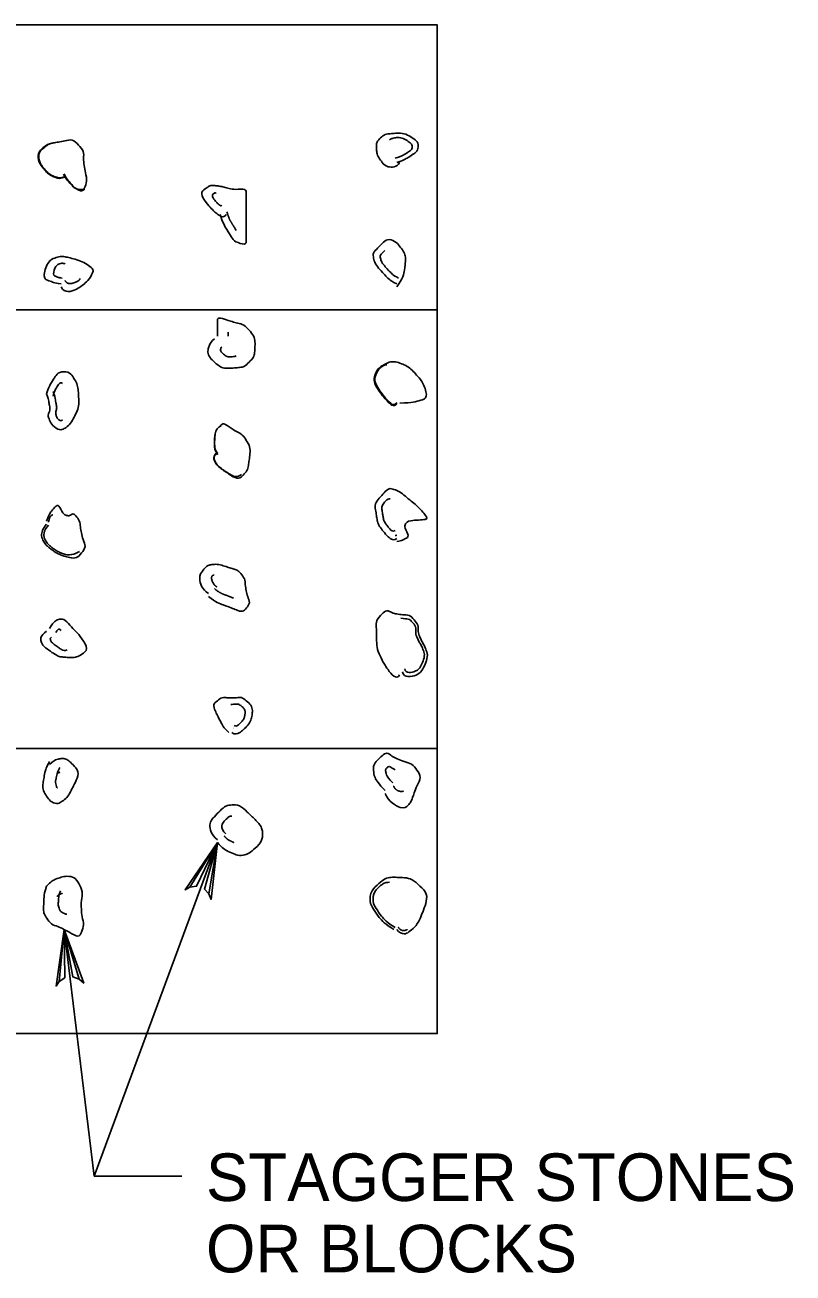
# Model space of a CAD drawing. Extents: x 636183 to 639890, y 299162 to 300538.
# Drawn here: x 638413.2 to 638461.6, y 300152.3 to 300230.9 of the extents above; entities that cross this region are included whole.
import ezdxf

# ---------------------------------------------------------------- set-up
doc = ezdxf.new("R2010")
doc.units = 0
doc.layers.add('Default', color=7, linetype='Continuous')

msp = doc.modelspace()

# ---------------------------------------------------------------- linework, layer by layer
at = {"layer": 'Default'}
for points in [[(638276.121, 300230.921), (638276.121, 300212.959), (638439.159, 300212.959), (638439.159, 300230.921), (638276.121, 300230.921)], [(638276.121, 300212.959), (638276.121, 300185.325), (638439.159, 300185.325), (638439.159, 300212.959), (638276.121, 300212.959)], [(638276.121, 300167.363), (638276.121, 300185.325), (638439.159, 300185.325), (638439.159, 300167.363), (638276.121, 300167.363)], [(638425.297, 300179.395), (638417.541, 300158.382)], [(638423.567, 300176.592), (638423.264, 300176.418), (638425.297, 300179.395), (638423.567, 300176.592), (638423.985, 300176.645), (638425.297, 300179.395), (638424.478, 300176.467), (638424.766, 300176.165), (638425.297, 300179.395), (638424.904, 300175.811), (638424.766, 300176.165)], [(638415.324, 300170.642), (638415.129, 300170.351), (638415.629, 300173.922), (638415.324, 300170.642), (638415.675, 300170.875), (638415.629, 300173.922), (638416.195, 300170.934), (638416.587, 300170.791), (638415.629, 300173.922), (638416.869, 300170.536), (638416.587, 300170.791)], [(638423.067, 300158.382), (638417.541, 300158.382), (638415.629, 300173.922)]]:
    msp.add_lwpolyline(points, dxfattribs=at)
for points, degree in [([(638415.639, 300221.323), (638415.466, 300221.243), (638415.253, 300221.255), (638415.072, 300221.323), (638414.773, 300221.434), (638414.529, 300221.635), (638414.324, 300221.882), (638414.035, 300222.23), (638413.949, 300222.886), (638414.324, 300223.195), (638414.567, 300223.395), (638414.84, 300223.459), (638415.114, 300223.51)], 3), ([(638415.629, 300221.35), (638415.462, 300221.272), (638415.257, 300221.284), (638415.081, 300221.35), (638414.789, 300221.46), (638414.551, 300221.656), (638414.351, 300221.898), (638414.072, 300222.237), (638413.985, 300222.865), (638414.351, 300223.174), (638414.634, 300223.412), (638414.948, 300223.491), (638415.263, 300223.54), (638415.678, 300223.604), (638416.172, 300223.745), (638416.541, 300223.356), (638416.921, 300222.956), (638416.835, 300222.512), (638416.905, 300222.08), (638416.982, 300221.605), (638417.106, 300221.068), (638416.905, 300220.62), (638416.802, 300220.389), (638416.342, 300220.614), (638416.175, 300220.802), (638415.973, 300221.03), (638415.761, 300221.254), (638415.629, 300221.532)], 3), ([(638436.79, 300222.262), (638436.619, 300221.936), (638435.949, 300221.93), (638435.694, 300222.262), (638435.465, 300222.56), (638435.338, 300222.866), (638435.33, 300223.174), (638435.325, 300223.355), (638435.338, 300223.543), (638435.512, 300223.722), (638435.807, 300224.027), (638436.116, 300224.058), (638436.424, 300224.086), (638436.841, 300224.124), (638437.291, 300224.017), (638437.702, 300223.722), (638437.984, 300223.52), (638437.954, 300222.983), (638437.702, 300222.81), (638437.363, 300222.578), (638437.001, 300222.373), (638436.606, 300222.262)], 3), ([(638436.152, 300223.685), (638436.247, 300223.747), (638436.342, 300223.78), (638436.438, 300223.798), (638436.759, 300223.857), (638437.109, 300223.745), (638437.428, 300223.517), (638437.595, 300223.398), (638437.577, 300223.08), (638437.428, 300222.978), (638437.145, 300222.784), (638436.842, 300222.613), (638436.511, 300222.52)], 3), ([(638416.933, 300220.583), (638416.763, 300220.518), (638416.335, 300220.577), (638416.159, 300220.777), (638415.955, 300221.008), (638415.738, 300221.236), (638415.604, 300221.518)], 3), ([(638425.845, 300218.978), (638425.7, 300218.696), (638425.166, 300219.093), (638424.93, 300219.344), (638424.613, 300219.684), (638424.172, 300220.348), (638424.567, 300220.62), (638424.738, 300220.739), (638424.926, 300220.824), (638425.115, 300220.802), (638425.418, 300220.766), (638425.723, 300220.697), (638426.027, 300220.62), (638426.403, 300220.525), (638427.12, 300220.641), (638427.12, 300220.256), (638427.12, 300219.891), (638427.12, 300219.526), (638427.12, 300219.16), (638427.12, 300218.552), (638427.12, 300217.944), (638427.12, 300217.336), (638427.12, 300217.026), (638426.375, 300217.256), (638426.209, 300217.521), (638425.917, 300217.985), (638425.631, 300218.454), (638425.479, 300218.978)], 3), ([(638425.582, 300219.57), (638425.538, 300219.484), (638425.375, 300219.605), (638425.303, 300219.681), (638425.142, 300219.852), (638424.914, 300220.198), (638425.119, 300220.33), (638425.127, 300220.335), (638425.134, 300220.338), (638425.142, 300220.337), (638425.171, 300220.333), (638425.199, 300220.327), (638425.228, 300220.321)], 3), ([(638426.487, 300217.97), (638426.257, 300218.349), (638426.026, 300218.719), (638425.902, 300219.14)], 2), ([(638436.606, 300214.601), (638436.329, 300214.733), (638436.107, 300214.898), (638435.876, 300215.149), (638435.542, 300215.509), (638435.231, 300215.876), (638435.148, 300216.243), (638435.081, 300216.539), (638435.406, 300216.862), (638435.694, 300217.154), (638435.995, 300217.46), (638436.518, 300217.311), (638436.79, 300216.973), (638437.031, 300216.673), (638437.167, 300216.369), (638437.154, 300216.061), (638437.13, 300215.516), (638436.992, 300214.949), (638436.606, 300214.419)], 3), ([(638415.445, 300214.601), (638415.196, 300214.633), (638414.95, 300214.702), (638414.715, 300214.783), (638414.246, 300214.945), (638414.603, 300216.072), (638415.081, 300216.243), (638415.371, 300216.346), (638415.699, 300216.319), (638415.993, 300216.243), (638416.442, 300216.126), (638416.905, 300215.96), (638417.269, 300215.695), (638417.571, 300215.474), (638417.197, 300214.857), (638416.905, 300214.601), (638416.533, 300214.274), (638415.651, 300213.975), (638415.445, 300214.419)], 3), ([(638436.728, 300214.967), (638436.507, 300215.071), (638436.33, 300215.203), (638436.145, 300215.402), (638435.886, 300215.682), (638435.644, 300215.967), (638435.579, 300216.252), (638435.544, 300216.402), (638435.709, 300216.564), (638435.855, 300216.712)], 3), ([(638415.512, 300214.965), (638415.393, 300214.98), (638415.274, 300215.013), (638415.162, 300215.052), (638414.898, 300215.144), (638415.096, 300215.789), (638415.369, 300215.874), (638415.478, 300215.908), (638415.597, 300215.897), (638415.708, 300215.874)], 3), ([(638416.629, 300214.937), (638416.629, 300214.777), (638415.811, 300214.54), (638415.692, 300214.822)], 2), ([(638425.297, 300211.317), (638425.297, 300211.621), (638425.297, 300211.925), (638425.297, 300212.229), (638425.297, 300212.533), (638425.925, 300212.319), (638426.209, 300212.229), (638426.589, 300212.108), (638426.969, 300212.061), (638427.302, 300211.683), (638427.618, 300211.326), (638427.682, 300210.949), (638427.668, 300210.587), (638427.657, 300210.279), (638427.598, 300209.973), (638427.302, 300209.675), (638427.007, 300209.377), (638426.7, 300209.335), (638426.39, 300209.311), (638425.973, 300209.278), (638425.531, 300209.302), (638425.115, 300209.675), (638424.806, 300209.951), (638424.672, 300210.304), (638424.749, 300210.587), (638424.8, 300210.777), (638424.93, 300210.977), (638425.115, 300211.135)], 3), ([(638425.974, 300211.317), (638425.974, 300211.395), (638425.974, 300211.473), (638425.974, 300211.552)], 2), ([(638426.483, 300210.078), (638426.44, 300210.047), (638426.397, 300210.032), (638426.354, 300210.025), (638426.115, 300209.989), (638425.858, 300210.019), (638425.619, 300210.235), (638425.527, 300210.318), (638425.488, 300210.423), (638425.511, 300210.509), (638425.522, 300210.55), (638425.549, 300210.594), (638425.589, 300210.628)], 3), ([(638436.626, 300207.057), (638436.44, 300206.768), (638435.91, 300207.302), (638435.657, 300207.639), (638435.349, 300208.048), (638435.106, 300208.564), (638435.279, 300208.959), (638435.382, 300209.194), (638435.599, 300209.4), (638435.857, 300209.537), (638436.214, 300209.726), (638436.637, 300209.692), (638436.988, 300209.537), (638437.361, 300209.372), (638437.656, 300209.099), (638437.925, 300208.786), (638438.269, 300208.388), (638438.615, 300207.409), (638438.116, 300207.266), (638437.681, 300207.142), (638437.238, 300207.11), (638436.794, 300207.077)], 3), ([(638436.606, 300207.121), (638436.43, 300206.85), (638435.932, 300207.352), (638435.694, 300207.669), (638435.397, 300208.065), (638435.163, 300208.563), (638435.33, 300208.945), (638435.427, 300209.168), (638435.623, 300209.386), (638435.876, 300209.493), (638435.911, 300209.508), (638435.948, 300209.5), (638435.984, 300209.493)], 3), ([(638414.533, 300207.669), (638414.644, 300208.064), (638414.847, 300208.426), (638415.081, 300208.763), (638415.291, 300209.065), (638415.946, 300209.093), (638416.175, 300208.763), (638416.417, 300208.415), (638416.523, 300208.047), (638416.541, 300207.669), (638416.562, 300207.246), (638416.556, 300206.814), (638416.357, 300206.391), (638416.178, 300206.009), (638415.905, 300205.632), (638415.629, 300205.479), (638415.378, 300205.34), (638414.87, 300205.676), (638414.715, 300206.027), (638414.583, 300206.328), (638414.775, 300206.643), (638414.715, 300206.939), (638414.666, 300207.184), (638414.624, 300207.43), (638414.533, 300207.669)], 3), ([(638414.939, 300207.52), (638415.021, 300207.814), (638415.151, 300208.087), (638415.346, 300208.335), (638415.387, 300208.386), (638415.482, 300208.374), (638415.535, 300208.335)], 3), ([(638415.528, 300206.041), (638415.444, 300205.905), (638415.187, 300206.124), (638415.146, 300206.271), (638415.08, 300206.509), (638415.193, 300206.758), (638415.146, 300206.992), (638415.09, 300207.269), (638415.042, 300207.548), (638414.939, 300207.819)], 3), ([(638425.297, 300203.837), (638425.136, 300204.129), (638425.102, 300204.448), (638425.115, 300204.749), (638425.128, 300205.068), (638425.21, 300205.403), (638425.479, 300205.661), (638425.684, 300205.859), (638425.988, 300205.613), (638426.209, 300205.479), (638426.551, 300205.271), (638426.884, 300205.115), (638427.12, 300204.749), (638427.381, 300204.346), (638427.354, 300203.892), (638427.302, 300203.474), (638427.263, 300203.155), (638427.19, 300202.829), (638426.938, 300202.562), (638426.654, 300202.259), (638426.17, 300202.519), (638425.845, 300202.744), (638425.541, 300202.953), (638425.239, 300203.184), (638425.115, 300203.474), (638425.045, 300203.635), (638425.14, 300203.883), (638425.297, 300204.022)], 3), ([(638425.313, 300203.847), (638425.154, 300204.135), (638425.118, 300204.451), (638425.131, 300204.749), (638425.144, 300205.062), (638425.207, 300205.42), (638425.49, 300205.643), (638425.505, 300205.654), (638425.523, 300205.636), (638425.538, 300205.629)], 3), ([(638426.812, 300202.601), (638426.543, 300202.373), (638426.141, 300202.563), (638425.852, 300202.76), (638425.549, 300202.964), (638425.255, 300203.193), (638425.133, 300203.478), (638425.066, 300203.635), (638425.159, 300203.876), (638425.31, 300204.01)], 3), ([(638436.606, 300198.548), (638436.361, 300198.379), (638435.943, 300198.773), (638435.694, 300199.096), (638435.463, 300199.394), (638435.379, 300199.695), (638435.33, 300200.008), (638435.274, 300200.361), (638435.207, 300200.746), (638435.512, 300201.102), (638435.805, 300201.443), (638436.127, 300201.754), (638436.424, 300201.65), (638436.79, 300201.521), (638437.154, 300201.215), (638437.518, 300200.92), (638437.874, 300200.631), (638438.209, 300200.285), (638438.429, 300200.008), (638438.667, 300199.71), (638437.31, 300199.73), (638437.154, 300199.46), (638437.051, 300199.282), (638437.431, 300198.685), (638437.154, 300198.548), (638436.978, 300198.461), (638436.795, 300198.4), (638436.606, 300198.366)], 3), ([(638414.533, 300199.642), (638414.642, 300199.986), (638414.84, 300200.334), (638415.081, 300200.556), (638415.288, 300200.746), (638415.55, 300200.08), (638415.811, 300200.008), (638415.968, 300199.965), (638416.223, 300200.167), (638416.357, 300200.008), (638416.64, 300199.672), (638416.651, 300199.289), (638416.723, 300198.914), (638416.803, 300198.498), (638417.049, 300198.034), (638416.723, 300197.636), (638416.44, 300197.29), (638415.966, 300197.343), (638415.629, 300197.454), (638415.382, 300197.536), (638415.138, 300197.648), (638414.899, 300197.818), (638414.673, 300197.979), (638414.483, 300198.154), (638414.351, 300198.366), (638414.163, 300198.669), (638414.263, 300199.183), (638414.533, 300199.46)], 3), ([(638436.509, 300199.057), (638436.374, 300198.963), (638436.143, 300199.182), (638436.005, 300199.361), (638435.83, 300199.587), (638435.766, 300199.815), (638435.728, 300200.052), (638435.687, 300200.313), (638435.649, 300200.6), (638435.864, 300200.862), (638435.967, 300200.988), (638436.083, 300201.068), (638436.203, 300201.065)], 3), ([(638414.648, 300199.596), (638414.699, 300199.768), (638414.753, 300199.97), (638414.922, 300200.054)], 2), ([(638416.601, 300197.74), (638416.319, 300197.585), (638415.94, 300197.484), (638415.648, 300197.581), (638415.419, 300197.656), (638415.192, 300197.761), (638414.971, 300197.919), (638414.769, 300198.063), (638414.6, 300198.219), (638414.483, 300198.407), (638414.313, 300198.68), (638414.402, 300199.144), (638414.646, 300199.393)], 3), ([(638436.601, 300198.771), (638436.573, 300198.757), (638436.544, 300198.747), (638436.514, 300198.741)], 2), ([(638424.749, 300195.082), (638424.312, 300195.356), (638424.07, 300196.143), (638424.385, 300196.542), (638424.522, 300196.716), (638424.717, 300196.878), (638424.93, 300196.906), (638425.291, 300196.953), (638425.668, 300196.846), (638426.027, 300196.724), (638426.29, 300196.634), (638426.549, 300196.597), (638426.757, 300196.36), (638427.051, 300196.024), (638427.044, 300195.636), (638427.12, 300195.264), (638427.193, 300194.912), (638427.394, 300194.498), (638427.12, 300194.17), (638426.893, 300193.897), (638426.485, 300194.062), (638426.209, 300194.17), (638425.713, 300194.363), (638425.188, 300194.542), (638424.749, 300194.9)], 3), ([(638425.274, 300195.504), (638425.047, 300195.632), (638424.865, 300196.2), (638425.082, 300196.261)], 2), ([(638426.314, 300194.799), (638425.906, 300194.969), (638425.473, 300195.11), (638425.11, 300195.402)], 2), ([(638414.715, 300192.892), (638414.856, 300193.132), (638415.068, 300193.374), (638415.263, 300193.44), (638415.594, 300193.553), (638416.016, 300193.066), (638416.357, 300192.71), (638416.747, 300192.303), (638417.205, 300191.548), (638416.723, 300191.25), (638416.426, 300191.066), (638416.113, 300191.044), (638415.811, 300191.068), (638415.568, 300191.088), (638415.324, 300191.099), (638415.081, 300191.25), (638414.665, 300191.511), (638414.245, 300191.832), (638414.169, 300192.164), (638414.131, 300192.333), (638414.336, 300192.568), (638414.533, 300192.71)], 3), ([(638436.79, 300189.974), (638436.594, 300189.596), (638435.935, 300190.424), (638435.694, 300190.886), (638435.409, 300191.432), (638435.332, 300191.983), (638435.33, 300192.528), (638435.328, 300192.959), (638435.281, 300193.399), (638435.694, 300193.806), (638435.977, 300194.086), (638436.31, 300193.864), (638436.606, 300193.806), (638436.98, 300193.733), (638437.405, 300193.77), (638437.702, 300193.44), (638437.997, 300193.111), (638437.918, 300192.693), (638438.066, 300192.346), (638438.17, 300192.101), (638438.329, 300191.861), (638438.429, 300191.616), (638438.588, 300191.229), (638438.458, 300190.736), (638438.248, 300190.338), (638438.037, 300189.941), (638437.046, 300189.734), (638436.972, 300190.156)], 3), ([(638436.859, 300193.544), (638437.101, 300193.486), (638437.374, 300193.513), (638437.568, 300193.307), (638437.849, 300193.009), (638437.771, 300192.606), (638437.909, 300192.282), (638438.008, 300192.049), (638438.161, 300191.821), (638438.257, 300191.589), (638438.393, 300191.255), (638438.282, 300190.83), (638438.1, 300190.488), (638437.937, 300190.181), (638437.17, 300190.02), (638437.112, 300190.348)], 3), ([(638415.114, 300192.639), (638415.168, 300192.73), (638415.247, 300192.832), (638415.323, 300192.846), (638415.36, 300192.853), (638415.403, 300192.803), (638415.441, 300192.768)], 3), ([(638415.823, 300191.54), (638415.684, 300191.472), (638415.467, 300191.551), (638415.316, 300191.667), (638415.09, 300191.841), (638414.807, 300192.02), (638414.761, 300192.222), (638414.753, 300192.259), (638414.798, 300192.311), (638414.842, 300192.342)], 3), ([(638426.027, 300186.327), (638425.691, 300186.636), (638425.491, 300187.04), (638425.297, 300187.421), (638425.162, 300187.685), (638424.998, 300188.102), (638425.297, 300188.333), (638425.601, 300188.568), (638425.905, 300188.517), (638426.209, 300188.514), (638426.512, 300188.512), (638426.816, 300188.586), (638427.12, 300188.333), (638427.441, 300188.065), (638427.528, 300187.712), (638427.484, 300187.421), (638427.436, 300187.105), (638427.239, 300186.798), (638426.938, 300186.509), (638426.726, 300186.304), (638426.401, 300186.189), (638426.209, 300186.327)], 3), ([(638426.151, 300188.093), (638426.17, 300188.107), (638426.189, 300188.104), (638426.209, 300188.105), (638426.415, 300188.109), (638426.621, 300188.152), (638426.828, 300187.98), (638427.012, 300187.827), (638427.063, 300187.625), (638427.038, 300187.458), (638427.006, 300187.25), (638426.876, 300187.049), (638426.678, 300186.859), (638426.583, 300186.767), (638426.437, 300186.714), (638426.351, 300186.776)], 3), ([(638426.324, 300186.608), (638426.322, 300186.609), (638426.321, 300186.611), (638426.319, 300186.612)], 2), ([(638435.876, 300182.677), (638435.462, 300183.091), (638435.171, 300183.53), (638435.148, 300183.955), (638435.131, 300184.262), (638435.363, 300184.576), (638435.694, 300184.867), (638435.983, 300185.121), (638436.313, 300184.809), (638436.606, 300184.685), (638437.069, 300184.489), (638437.583, 300184.382), (638437.884, 300183.955), (638438.185, 300183.528), (638437.872, 300182.969), (638437.702, 300182.495), (638437.607, 300182.232), (638437.501, 300181.948), (638437.336, 300181.765), (638437.004, 300181.398), (638436.092, 300181.983), (638435.876, 300182.495)], 3), ([(638414.715, 300184.319), (638414.959, 300184.535), (638415.202, 300184.663), (638415.445, 300184.685), (638415.689, 300184.707), (638415.932, 300184.561), (638416.175, 300184.319), (638416.609, 300183.886), (638416.402, 300183.312), (638416.175, 300182.861), (638415.994, 300182.499), (638415.742, 300182.135), (638415.445, 300181.949), (638415.196, 300181.793), (638414.74, 300181.997), (638414.533, 300182.313), (638414.3, 300182.67), (638414.287, 300183.053), (638414.351, 300183.407), (638414.418, 300183.775), (638414.501, 300184.149), (638414.715, 300184.501)], 3), ([(638415.21, 300182.843), (638415.208, 300182.843), (638415.201, 300182.843), (638415.199, 300182.847), (638415.119, 300183.011), (638415.087, 300183.185), (638415.116, 300183.347), (638415.163, 300183.612), (638415.222, 300183.881), (638415.376, 300184.135)], 3), ([(638436.357, 300183.158), (638436.102, 300183.415), (638435.924, 300183.684), (638435.908, 300183.946), (638435.904, 300184.008), (638435.951, 300184.072), (638436.018, 300184.132), (638436.131, 300184.233), (638436.262, 300184.113), (638436.373, 300184.063), (638436.42, 300184.042), (638436.464, 300184.033), (638436.504, 300183.987)], 3), ([(638415.224, 300183.743), (638415.256, 300183.785), (638415.329, 300183.837), (638415.362, 300183.812)], 2), ([(638437.043, 300182.645), (638436.898, 300182.579), (638436.498, 300182.739), (638436.412, 300182.96)], 2), ([(638425.297, 300179.577), (638424.898, 300179.887), (638424.717, 300180.616), (638425.115, 300181.035), (638425.47, 300181.41), (638425.84, 300181.751), (638426.209, 300181.765), (638426.691, 300181.784), (638427.19, 300181.319), (638427.668, 300180.853), (638428.175, 300180.36), (638428.175, 300179.477), (638427.668, 300179.029), (638427.299, 300178.703), (638426.773, 300178.526), (638426.39, 300178.665), (638426.012, 300178.804), (638425.604, 300179.035), (638425.297, 300179.395)], 3), ([(638425.842, 300179.941), (638425.622, 300180.113), (638425.521, 300180.517), (638425.741, 300180.749), (638425.896, 300180.913), (638426.057, 300181.061), (638426.218, 300181.067)], 3), ([(638426.342, 300179.402), (638426.128, 300179.5), (638425.897, 300179.612), (638425.73, 300179.812)], 2), ([(638414.533, 300176.657), (638414.8, 300176.943), (638415.132, 300177.118), (638415.445, 300177.205), (638415.785, 300177.3), (638416.322, 300177.22), (638416.541, 300176.839), (638416.854, 300176.295), (638416.69, 300175.747), (638416.723, 300175.2), (638416.752, 300174.715), (638416.923, 300174.218), (638416.723, 300173.74), (638416.571, 300173.377), (638415.959, 300173.755), (638415.629, 300173.922), (638415.237, 300174.119), (638414.815, 300174.224), (638414.533, 300174.652), (638414.334, 300174.954), (638414.337, 300175.258), (638414.351, 300175.564), (638414.369, 300175.928), (638414.398, 300176.294), (638414.533, 300176.657)], 3), ([(638436.424, 300173.922), (638435.881, 300174.231), (638435.451, 300174.723), (638435.148, 300175.2), (638434.866, 300175.643), (638434.986, 300176.398), (638435.512, 300176.839), (638435.873, 300177.142), (638436.243, 300177.214), (638436.606, 300177.205), (638437.096, 300177.194), (638437.586, 300177.103), (638438.066, 300176.657), (638438.573, 300176.185), (638438.446, 300175.525), (638438.248, 300175.015), (638438.059, 300174.532), (638437.757, 300174.044), (638437.336, 300173.74), (638437.133, 300173.594), (638436.766, 300173.711), (638436.606, 300173.922)], 3), ([(638415.818, 300174.88), (638415.735, 300174.872), (638415.417, 300175.01), (638415.346, 300175.195), (638415.298, 300175.322), (638415.264, 300175.449), (638415.27, 300175.577), (638415.283, 300175.839), (638415.304, 300176.102), (638415.401, 300176.363)], 3), ([(638436.511, 300174.048), (638436.002, 300174.338), (638435.597, 300174.799), (638435.311, 300175.246), (638435.056, 300175.645), (638435.175, 300176.347), (638435.641, 300176.724), (638435.807, 300176.858), (638435.979, 300176.879), (638436.152, 300176.895)], 3), ([(638415.178, 300175.99), (638415.277, 300176.098), (638415.407, 300176.156), (638415.528, 300176.199)], 2), ([(638437.273, 300173.91), (638437.127, 300173.837), (638436.819, 300173.886), (638436.707, 300174.051)], 2)]:
    msp.add_open_spline(points, degree=degree, dxfattribs=at)

# ---------------------------------------------------------------- texts
for s, height, p in [('STAGGER STONES', 2.99804, (638424.58, 300156.808)), ('OR BLOCKS', 2.998, (638424.58, 300152.311))]:
    msp.add_text(s, height=height, dxfattribs=at).set_placement(p)

doc.saveas('drawing.dxf')
